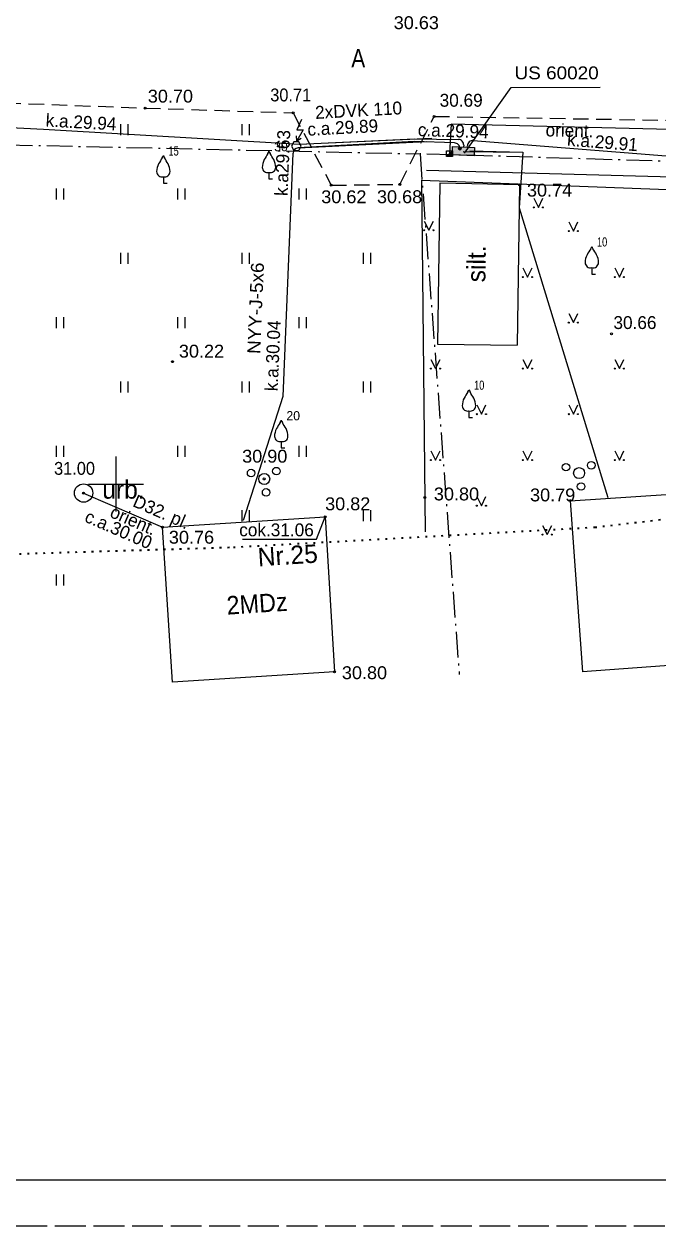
# Model space of a CAD drawing. Extents: x 380758 to 381729, y 283236 to 283533.
# Drawn here: x 380845 to 380879.5, y 283259.6 to 283325 of the extents above; entities that cross this region are included whole.
import ezdxf
from ezdxf.enums import TextEntityAlignment as Align

# ---------------------------------------------------------------- set-up
doc = ezdxf.new("R2010")
doc.units = 0
doc.header["$LTSCALE"] = 0.28
doc.header["$PDMODE"] = 32
doc.header["$PDSIZE"] = 0.14
for name, pattern in [('DOT_DASHED', [7.7, 5, -1.2, 0.3, -1.2]), ('DOTTED', [1.5, 0.3, -1.2]), ('LONG_DASHED', [7.5, 6, -1.5]), ('MEDIUM_DASHED', [4.5, 3, -1.5])]:
    doc.linetypes.add(name, pattern=pattern)
for name, color, linetype, lineweight in [('1', 7, 'Continuous', 13), ('12', 7, 'Continuous', 13), ('17', 7, 'Continuous', 13), ('18', 7, 'Continuous', 13), ('23', 7, 'Continuous', 13), ('25', 7, 'DOTTED', 35), ('29', 7, 'DOT_DASHED', 25), ('30', 7, 'Continuous', 13), ('35', 7, 'Continuous', 13), ('37', 7, 'MEDIUM_DASHED', 13), ('39', 7, 'Continuous', 13), ('4', 7, 'Continuous', 13), ('40', 7, 'Continuous', 25), ('42', 7, 'Continuous', 13), ('49', 7, 'Continuous', 13), ('58', 7, 'Continuous', 25), ('6', 7, 'Continuous', 13), ('63', 7, 'Continuous', 13), ('7', 7, 'Continuous', 13), ('9', 7, 'Continuous', 13)]:
    doc.layers.add(name, color=color, linetype=linetype, lineweight=lineweight)
doc.layers.add('5', color=7, linetype='Continuous')

msp = doc.modelspace()

# ---------------------------------------------------------------- hatches: boundary and pattern name
at = {"layer": '18'}
msp.add_hatch(color=256, dxfattribs=at).paths.add_polyline_path([(380868.316, 283318.368), (380869.514, 283318.308), (380869.492, 283317.858), (380868.294, 283317.918)])
at = {"layer": '49'}
msp.add_hatch(color=256, dxfattribs=at).paths.add_polyline_path([(380867.986, 283317.817), (380868.306, 283318.133), (380868.306, 283317.817)])
at = {"layer": '6'}
msp.add_hatch(color=256, dxfattribs=at).paths.add_polyline_path([(380848.2905, 283299.512, 1), (380848.1844, 283299.512, 1)])

# ---------------------------------------------------------------- linework, layer by layer
at = {"layer": '1'}
for p, q in [((380858.325, 283316.953), (380858.325, 283316.601)), ((380866.889, 283317.067), (380881.418, 283316.689)), ((380852.577, 283316.721), (380852.577, 283316.369)), ((380852.577, 283316.369), (380852.777, 283316.369)), ((380858.325, 283316.601), (380858.525, 283316.601)), ((380875.893, 283311.774), (380875.893, 283311.422)), ((380875.893, 283311.422), (380876.093, 283311.422)), ((380869.206, 283303.981), (380869.206, 283303.629)), ((380869.206, 283303.629), (380869.406, 283303.629)), ((380858.992, 283302.32), (380858.992, 283301.968)), ((380858.992, 283301.968), (380859.192, 283301.968))]:
    msp.add_line(p, q, dxfattribs=at)
for centre, radius in [((380875.8624, 283301.0202), 0.2066), ((380857.3518, 283300.6012), 0.2041), ((380858.0659, 283300.2773), 0.3006), ((380858.7274, 283300.7022), 0.2066), ((380874.4868, 283300.9192), 0.2041), ((380875.2009, 283300.5953), 0.3006), ((380875.3042, 283299.8678), 0.2045), ((380858.1692, 283299.5498), 0.2045)]:
    msp.add_circle(centre, radius, dxfattribs=at)
for centre, radius, start, end in [((380865.2018, 283309.973), 14.8796, 148.48442, 149.99014), ((380852.1598, 283318.0069), 0.4394, 324.38368, 341.71196), ((380852.9942, 283318.0069), 0.4394, 198.28804, 215.61632), ((380839.9522, 283309.973), 14.8796, 30.00986, 31.51558), ((380858.8494, 283317.2257), 0.8904, 151.75702, 179.91384), ((380870.9498, 283310.205), 14.8796, 148.48442, 149.99014), ((380857.9078, 283318.2389), 0.4394, 324.38368, 341.71196), ((380858.7422, 283318.2389), 0.4394, 198.28804, 215.61632), ((380845.7002, 283310.205), 14.8796, 30.00986, 31.51558), ((380857.8006, 283317.2257), 0.8904, 0.08616, 28.24298), ((380853.1014, 283316.9937), 0.8904, 151.75702, 179.91384), ((380852.5006, 283317.0005), 0.2897, 181.07816, 285.2823), ((380852.6534, 283317.0005), 0.2897, 254.7177, 358.92184), ((380852.0526, 283316.9937), 0.8904, 0.08616, 28.24298), ((380858.2486, 283317.2325), 0.2897, 181.07816, 285.2823), ((380858.4014, 283317.2325), 0.2897, 254.7177, 358.92184), ((380875.4758, 283313.0599), 0.4394, 324.38368, 341.71196), ((380876.3102, 283313.0599), 0.4394, 198.28804, 215.61632), ((380876.4174, 283312.0467), 0.8904, 151.75702, 179.91384), ((380888.5178, 283305.026), 14.8796, 148.48442, 149.99014), ((380863.2682, 283305.026), 14.8796, 30.00986, 31.51558), ((380875.3686, 283312.0467), 0.8904, 0.08616, 28.24298), ((380875.8166, 283312.0535), 0.2897, 181.07816, 285.2823), ((380875.9694, 283312.0535), 0.2897, 254.7177, 358.92184), ((380868.7888, 283305.2669), 0.4394, 324.38368, 341.71196), ((380869.6232, 283305.2669), 0.4394, 198.28804, 215.61632), ((380869.7304, 283304.2537), 0.8904, 151.75702, 179.91384), ((380881.8308, 283297.233), 14.8796, 148.48442, 149.99014), ((380856.5812, 283297.233), 14.8796, 30.00986, 31.51558), ((380868.6816, 283304.2537), 0.8904, 0.08616, 28.24298), ((380869.1296, 283304.2605), 0.2897, 181.07816, 285.2823), ((380869.2824, 283304.2605), 0.2897, 254.7177, 358.92184), ((380871.6168, 283295.572), 14.8796, 148.48442, 149.99014), ((380858.5748, 283303.6059), 0.4394, 324.38368, 341.71196), ((380859.4092, 283303.6059), 0.4394, 198.28804, 215.61632), ((380846.3672, 283295.572), 14.8796, 30.00986, 31.51558), ((380859.5164, 283302.5927), 0.8904, 151.75702, 179.91384), ((380858.9156, 283302.5995), 0.2897, 181.07816, 285.2823), ((380859.0684, 283302.5995), 0.2897, 254.7177, 358.92184), ((380858.4676, 283302.5927), 0.8904, 0.08616, 28.24298)]:
    msp.add_arc(centre, radius, start, end, dxfattribs=at)
at = {"layer": '12'}
msp.add_line((380859.841, 283318.678), (380860.082, 283318.817), dxfattribs=at)
msp.add_lwpolyline([(380860.09, 283319.84), (380859.841, 283319.277), (380860.177, 283319.277), (380859.841, 283318.678), (380859.819, 283318.948)], dxfattribs=at)
msp.add_lwpolyline([(380859.685, 283318.148), (380859.951, 283318.148), (380860.084, 283318.378), (380859.951, 283318.609), (380859.685, 283318.609), (380859.552, 283318.378)], close=True, dxfattribs=at)
at = {"layer": '17'}
msp.add_lwpolyline([(380880.905, 283319.277), (380868.247, 283319.581), (380868.146, 283317.975)], dxfattribs=at)
at = {"layer": '18'}
msp.add_lwpolyline([(380868.316, 283318.368), (380869.514, 283318.308), (380869.492, 283317.858), (380868.294, 283317.918)], close=True, dxfattribs=at)
at = {"layer": '23'}
for p, q in [((380850.268, 283318.984), (380850.268, 283319.584)), ((380850.668, 283318.984), (380850.668, 283319.584)), ((380856.868, 283318.984), (380856.868, 283319.584)), ((380857.268, 283318.984), (380857.268, 283319.584)), ((380846.768, 283315.484), (380846.768, 283316.084)), ((380847.168, 283315.484), (380847.168, 283316.084)), ((380853.368, 283315.484), (380853.368, 283316.084)), ((380853.768, 283315.484), (380853.768, 283316.084)), ((380859.968, 283315.484), (380859.968, 283316.084)), ((380860.368, 283315.484), (380860.368, 283316.084)), ((380850.268, 283311.984), (380850.268, 283312.584)), ((380850.668, 283311.984), (380850.668, 283312.584)), ((380856.868, 283311.984), (380856.868, 283312.584)), ((380857.268, 283311.984), (380857.268, 283312.584)), ((380863.468, 283311.984), (380863.468, 283312.584)), ((380863.868, 283311.984), (380863.868, 283312.584)), ((380846.768, 283308.484), (380846.768, 283309.084)), ((380847.168, 283308.484), (380847.168, 283309.084)), ((380853.368, 283308.484), (380853.368, 283309.084)), ((380853.768, 283308.484), (380853.768, 283309.084)), ((380859.968, 283308.484), (380859.968, 283309.084)), ((380860.368, 283308.484), (380860.368, 283309.084)), ((380850.268, 283304.984), (380850.268, 283305.584)), ((380850.668, 283304.984), (380850.668, 283305.584)), ((380856.868, 283304.984), (380856.868, 283305.584)), ((380857.268, 283304.984), (380857.268, 283305.584)), ((380863.468, 283304.984), (380863.468, 283305.584)), ((380863.868, 283304.984), (380863.868, 283305.584)), ((380846.768, 283301.484), (380846.768, 283302.084)), ((380847.168, 283301.484), (380847.168, 283302.084)), ((380853.368, 283301.484), (380853.368, 283302.084)), ((380853.768, 283301.484), (380853.768, 283302.084)), ((380859.968, 283301.484), (380859.968, 283302.084)), ((380860.368, 283301.484), (380860.368, 283302.084)), ((380856.868, 283297.984), (380856.868, 283298.584)), ((380857.268, 283297.984), (380857.268, 283298.584)), ((380863.468, 283297.984), (380863.468, 283298.584)), ((380863.868, 283297.984), (380863.868, 283298.584)), ((380846.768, 283294.484), (380846.768, 283295.084)), ((380847.168, 283294.484), (380847.168, 283295.084))]:
    msp.add_line(p, q, dxfattribs=at)
for points in [[(380872.733, 283315.546), (380872.983, 283315.046), (380873.233, 283315.546)], [(380866.774, 283314.305), (380867.024, 283313.805), (380867.274, 283314.305)], [(380874.638, 283314.259), (380874.888, 283313.759), (380875.138, 283314.259)], [(380872.138, 283311.759), (380872.388, 283311.259), (380872.638, 283311.759)], [(380877.142, 283311.759), (380877.392, 283311.259), (380877.642, 283311.759)], [(380874.638, 283309.281), (380874.888, 283308.781), (380875.138, 283309.281)], [(380867.134, 283306.781), (380867.384, 283306.281), (380867.634, 283306.781)], [(380872.138, 283306.781), (380872.388, 283306.281), (380872.638, 283306.781)], [(380877.142, 283306.781), (380877.392, 283306.281), (380877.642, 283306.781)], [(380869.634, 283304.303), (380869.884, 283303.803), (380870.134, 283304.303)], [(380874.638, 283304.303), (380874.888, 283303.803), (380875.138, 283304.303)], [(380867.134, 283301.803), (380867.384, 283301.303), (380867.634, 283301.803)], [(380872.138, 283301.803), (380872.388, 283301.303), (380872.638, 283301.803)], [(380877.142, 283301.803), (380877.392, 283301.303), (380877.642, 283301.803)], [(380869.634, 283299.325), (380869.884, 283298.825), (380870.134, 283299.325)], [(380873.21, 283297.751), (380873.46, 283297.251), (380873.71, 283297.751)]]:
    msp.add_lwpolyline(points, dxfattribs=at)
for centre, radius in [((380872.7327, 283315.0453), 0.028), ((380873.2327, 283315.0453), 0.0263), ((380866.7735, 283313.8049), 0.028), ((380867.2735, 283313.8049), 0.0263), ((380874.6379, 283313.7587), 0.028), ((380875.1379, 283313.7587), 0.0263), ((380872.1379, 283311.2587), 0.028), ((380872.6379, 283311.2587), 0.0263), ((380877.1419, 283311.2587), 0.028), ((380877.6419, 283311.2587), 0.0263), ((380874.6379, 283308.7807), 0.028), ((380875.1379, 283308.7807), 0.0263), ((380867.1339, 283306.2807), 0.028), ((380867.6339, 283306.2807), 0.0263), ((380872.1379, 283306.2807), 0.028), ((380872.6379, 283306.2807), 0.0263), ((380877.1419, 283306.2807), 0.028), ((380877.6419, 283306.2807), 0.0263), ((380869.6339, 283303.8027), 0.028), ((380870.1339, 283303.8027), 0.0263), ((380874.6379, 283303.8027), 0.028), ((380875.1379, 283303.8027), 0.0263), ((380867.1339, 283301.3027), 0.028), ((380867.6339, 283301.3027), 0.0263), ((380872.1379, 283301.3027), 0.028), ((380872.6379, 283301.3027), 0.0263), ((380877.1419, 283301.3027), 0.028), ((380877.6419, 283301.3027), 0.0263), ((380869.6339, 283298.8247), 0.028), ((380870.1339, 283298.8247), 0.0263), ((380873.2094, 283297.2503), 0.028), ((380873.7094, 283297.2503), 0.0263)]:
    msp.add_circle(centre, radius, dxfattribs=at)
at = {"layer": '25'}
msp.add_lwpolyline([(381026.117, 283349.86), (380986.913, 283346.195), (380951.371, 283344.43), (380924.511, 283343.073), (380900.74, 283340.36), (380898.299, 283339.817), (380883.648, 283341.174), (380816.227, 283340.496), (380794.658, 283339.817), (380797.642, 283326.649), (380792.352, 283320.811), (380793.844, 283316.603), (380786.796, 283296.295), (380803.346, 283294.938), (380856.387, 283296.567), (380876.057, 283297.653), (380895.999, 283299.961), (380927.606, 283299.553), (380945.042, 283301.724), (380965.254, 283306.611), (380999.033, 283308.647)], dxfattribs=at)
at = {"layer": '29'}
for p, q in [((380885.683, 283317.385), (380866.546, 283317.96)), ((380866.546, 283317.96), (380868.677, 283289.644))]:
    msp.add_line(p, q, dxfattribs=at)
msp.add_lwpolyline([(380792.473, 283287.96), (380799.228, 283311.375), (380809.317, 283319.223), (380866.546, 283317.96)], dxfattribs=at)
at = {"layer": '30'}
for points in [[(380850, 283301.5), (380850, 283300), (380850, 283298.5)], [(380848.5, 283300), (380850, 283300), (380851.5, 283300)]]:
    msp.add_lwpolyline(points, dxfattribs=at)
at = {"layer": '35'}
for q in [(380866.829, 283297.398), (380881.489, 283315.974)]:
    msp.add_line((380866.633, 283316.533), q, dxfattribs=at)
at = {"layer": '37'}
msp.add_line((380867.312, 283320), (380881.032, 283319.774), dxfattribs=at)
for points in [[(380817.606, 283321.48), (380835.175, 283321.069), (380851.583, 283320.452)], [(380851.583, 283320.452), (380859.637, 283320.197), (380861.703, 283316.256), (380865.446, 283316.303), (380867.312, 283320)]]:
    msp.add_lwpolyline(points, dxfattribs=at)
at = {"layer": '39'}
msp.add_line((380871.95, 283316.28), (380871.827, 283307.55), dxfattribs=at)
msp.add_lwpolyline([(380871.95, 283316.28), (380867.622, 283316.377), (380867.498, 283307.611), (380871.827, 283307.55)], dxfattribs=at)
at = {"layer": '40'}
msp.add_line((380874.711, 283299.097), (380875.39, 283289.783), dxfattribs=at)
msp.add_lwpolyline([(380874.711, 283299.097), (380887.36, 283299.928), (380888.032, 283290.705), (380875.39, 283289.783)], dxfattribs=at)
msp.add_lwpolyline([(380852.524, 283297.648), (380861.38, 283298.222), (380861.893, 283289.79), (380853.07, 283289.218)], close=True, dxfattribs=at)
at = {"layer": '42', "lineweight": 25}
msp.add_lwpolyline([(380856.879, 283297.007), (380860.91, 283297.007), (380861.38, 283298.215)], dxfattribs=at)
at = {"layer": '49'}
msp.add_lwpolyline([(380867.986, 283317.817), (380868.306, 283318.133), (380868.306, 283317.817)], close=True, dxfattribs=at)
msp.add_lwpolyline([(380867.986, 283317.817), (380867.986, 283318.133), (380868.306, 283318.133)], dxfattribs=at)
at = {"layer": '58'}
for centre in [(380851.583, 283320.4521), (380859.637, 283320.1971), (380867.312, 283320.0001), (380861.703, 283316.2561), (380865.446, 283316.3031), (380871.95, 283316.2801), (380876.956, 283308.1711), (380853.068, 283306.6581), (380858.066, 283300.2771), (380866.81, 283299.2631), (380874.711, 283299.0971), (380861.38, 283298.2221), (380852.524, 283297.6481), (380861.893, 283289.7901)]:
    msp.add_circle(centre, 0.0534, dxfattribs=at)
at = {"layer": '6'}
for centre, radius in [((380848.238, 283299.5125), 0.5), ((380848.2375, 283299.512), 0.053)]:
    msp.add_circle(centre, radius, dxfattribs=at)
at = {"layer": '63', "linetype": 'LONG_DASHED'}
msp.add_lwpolyline([(381352.477, 283469.645), (380758.477, 283469.645), (380758.477, 283259.645), (381352.477, 283259.645)], dxfattribs=at)
at = {"layer": '63'}
msp.add_lwpolyline([(381349.977, 283262.145), (380768.477, 283262.145), (380768.477, 283467.145)], dxfattribs=at)
at = {"layer": '7'}
for p, q in [((380859.971, 283318.483), (380867.195, 283318.812)), ((380859.938, 283318.285), (380866.873, 283318.626)), ((380868.92, 283318.435), (380868.915, 283318.338)), ((380869.115, 283318.328), (380869.119, 283318.4)), ((380869.252, 283318.119), (380872.139, 283318.052)), ((380871.94, 283315.03), (380876.768, 283299.275))]:
    msp.add_line(p, q, dxfattribs=at)
for points in [[(380869.442, 283318.684), (380881.082, 283317.757), (380886.903, 283317.181), (380889.169, 283316.944), (380892.982, 283316.903), (380901.792, 283317.99), (380921.781, 283319.424), (380942.599, 283321.686), (380951.056, 283322.558)], [(380868.956, 283318.006), (380871.504, 283321.577), (380876.349, 283321.592)], [(380815.574, 283320.809), (380827.86, 283320.238), (380846.055, 283319.297), (380859.988, 283318.493), (380866.245, 283318.786), (380868.63, 283318.749)], [(380868.421, 283318.556), (380866.223, 283318.63), (380859.916, 283318.289)], [(380859.632, 283318.002), (380859.072, 283304.769), (380856.921, 283298.011)], [(380868.895, 283318.09), (380872.139, 283318.052), (380871.94, 283315.03)]]:
    msp.add_lwpolyline(points, dxfattribs=at)
for centre, start, end in [((380859.932, 283317.9892), 93.0948, 177.57578), ((380868.4105, 283318.2565), 357.14037, 88.08366), ((380868.6204, 283318.4495), 357.14037, 88.08366), ((380869.4182, 283318.3849), 85.44708, 177.14037)]:
    msp.add_arc(centre, 0.3, start, end, dxfattribs=at)
msp.add_point((380868.71, 283318.241), dxfattribs=at)
at = {"layer": '9'}
msp.add_line((380848.238, 283299.513), (380852.524, 283297.648), dxfattribs=at)

# ---------------------------------------------------------------- texts
at = {"layer": '1', "width": 0.75}
for s, p in [('15', (380852.857, 283317.869)), ('10', (380876.173, 283312.922)), ('10', (380869.486, 283305.129))]:
    msp.add_text(s, height=0.5, dxfattribs=at).set_placement(p)
at = {"layer": '1'}
for s, p in [('30', (380858.605, 283318.101)), ('20', (380859.272, 283303.468))]:
    msp.add_text(s, height=0.5, dxfattribs=at).set_placement(p)
at = {"layer": '17'}
msp.add_text('orient.', height=0.7, rotation=358.626, dxfattribs=at).set_placement((380874.6711, 283318.8842), align=Align.CENTER)
at = {"layer": '37', "width": 0.85}
msp.add_text('A', height=1, dxfattribs=at).set_placement((380863.1835, 283322.666), align=Align.CENTER)
at = {"layer": '4'}
msp.add_text('silt.', height=1, rotation=89.193, dxfattribs=at).set_placement((380870.096, 283310.969))
at = {"layer": '4', "width": 0.95}
msp.add_text('2MDz', height=1, rotation=3.708, dxfattribs=at).set_placement((380856.053, 283292.896))
at = {"layer": '42'}
msp.add_text('cok.31.06', height=0.7, dxfattribs=at).set_placement((380856.705, 283297.159))
at = {"layer": '5'}
msp.add_text('Nr.25', height=1, rotation=3.708, dxfattribs=at).set_placement((380857.745, 283295.521))
at = {"layer": '58'}
for s, width, p in [('30.63', 1.05, (380865.113, 283324.747)), ('30.70', 1.05, (380851.732, 283320.752)), ('30.71', 0.95, (380858.395, 283320.816)), ('30.74', 1.05, (380872.363, 283315.64)), ('30.62', 1.05, (380861.169, 283315.277)), ('30.68', 1.05, (380864.201, 283315.28)), ('30.22', 1.05, (380853.423, 283306.88)), ('30.90', 1.05, (380856.866, 283301.166)), ('30.82', 1.05, (380861.38, 283298.577)), ('30.80', 1.05, (380867.298, 283299.112)), ('30.79', 1.05, (380872.531, 283299.059)), ('30.76', 1.05, (380852.879, 283296.758)), ('30.80', 1.05, (380862.292, 283289.389))]:
    msp.add_text(s, height=0.7, dxfattribs=dict(at, width=width)).set_placement(p)
for s, p in [('30.69', (380867.612, 283320.526)), ('30.66', (380877.068, 283308.434))]:
    msp.add_text(s, height=0.7, dxfattribs=at).set_placement(p)
at = {"layer": '6', "width": 0.95}
msp.add_text('31.00', height=0.7, dxfattribs=at).set_placement((380846.632, 283300.504))
at = {"layer": '6'}
msp.add_text('urb.', height=1, dxfattribs=at).set_placement((380849.255, 283299.207))
at = {"layer": '7', "width": 1.1}
msp.add_text('US 60020', height=0.7, dxfattribs=at).set_placement((380871.686, 283322.018))
at = {"layer": '7'}
for s, rotation, p in [('2xDVK 110', 3.152, (380860.854, 283319.859)), ('k.a.29.94', 356.697, (380846.159, 283319.455)), ('c.a.29.89', 3.095, (380860.434, 283318.944)), ('c.a.29.94', 358.084, (380866.415, 283318.933)), ('k.a29.63', 87.576, (380859.335, 283315.66)), ('k.a.29.91', 355.447, (380874.528, 283318.409)), ('k.a.30.04', 87.576, (380858.797, 283305.041))]:
    msp.add_text(s, height=0.7, rotation=rotation, dxfattribs=at).set_placement(p)
at = {"layer": '7', "width": 1.1}
msp.add_text('NYY-J-5x6', height=0.7, rotation=87.538, dxfattribs=at).set_placement((380857.842, 283307.065))
at = {"layer": '9'}
for s, p in [('D32. pl.', (380852.3379, 283298.1662)), ('orient.', (380850.8049, 283297.7111)), ('c.a.30.00', (380850.0029, 283297.2088))]:
    msp.add_text(s, height=0.7, rotation=336.49, dxfattribs=at).set_placement(p, align=Align.CENTER)

doc.saveas('drawing.dxf')
